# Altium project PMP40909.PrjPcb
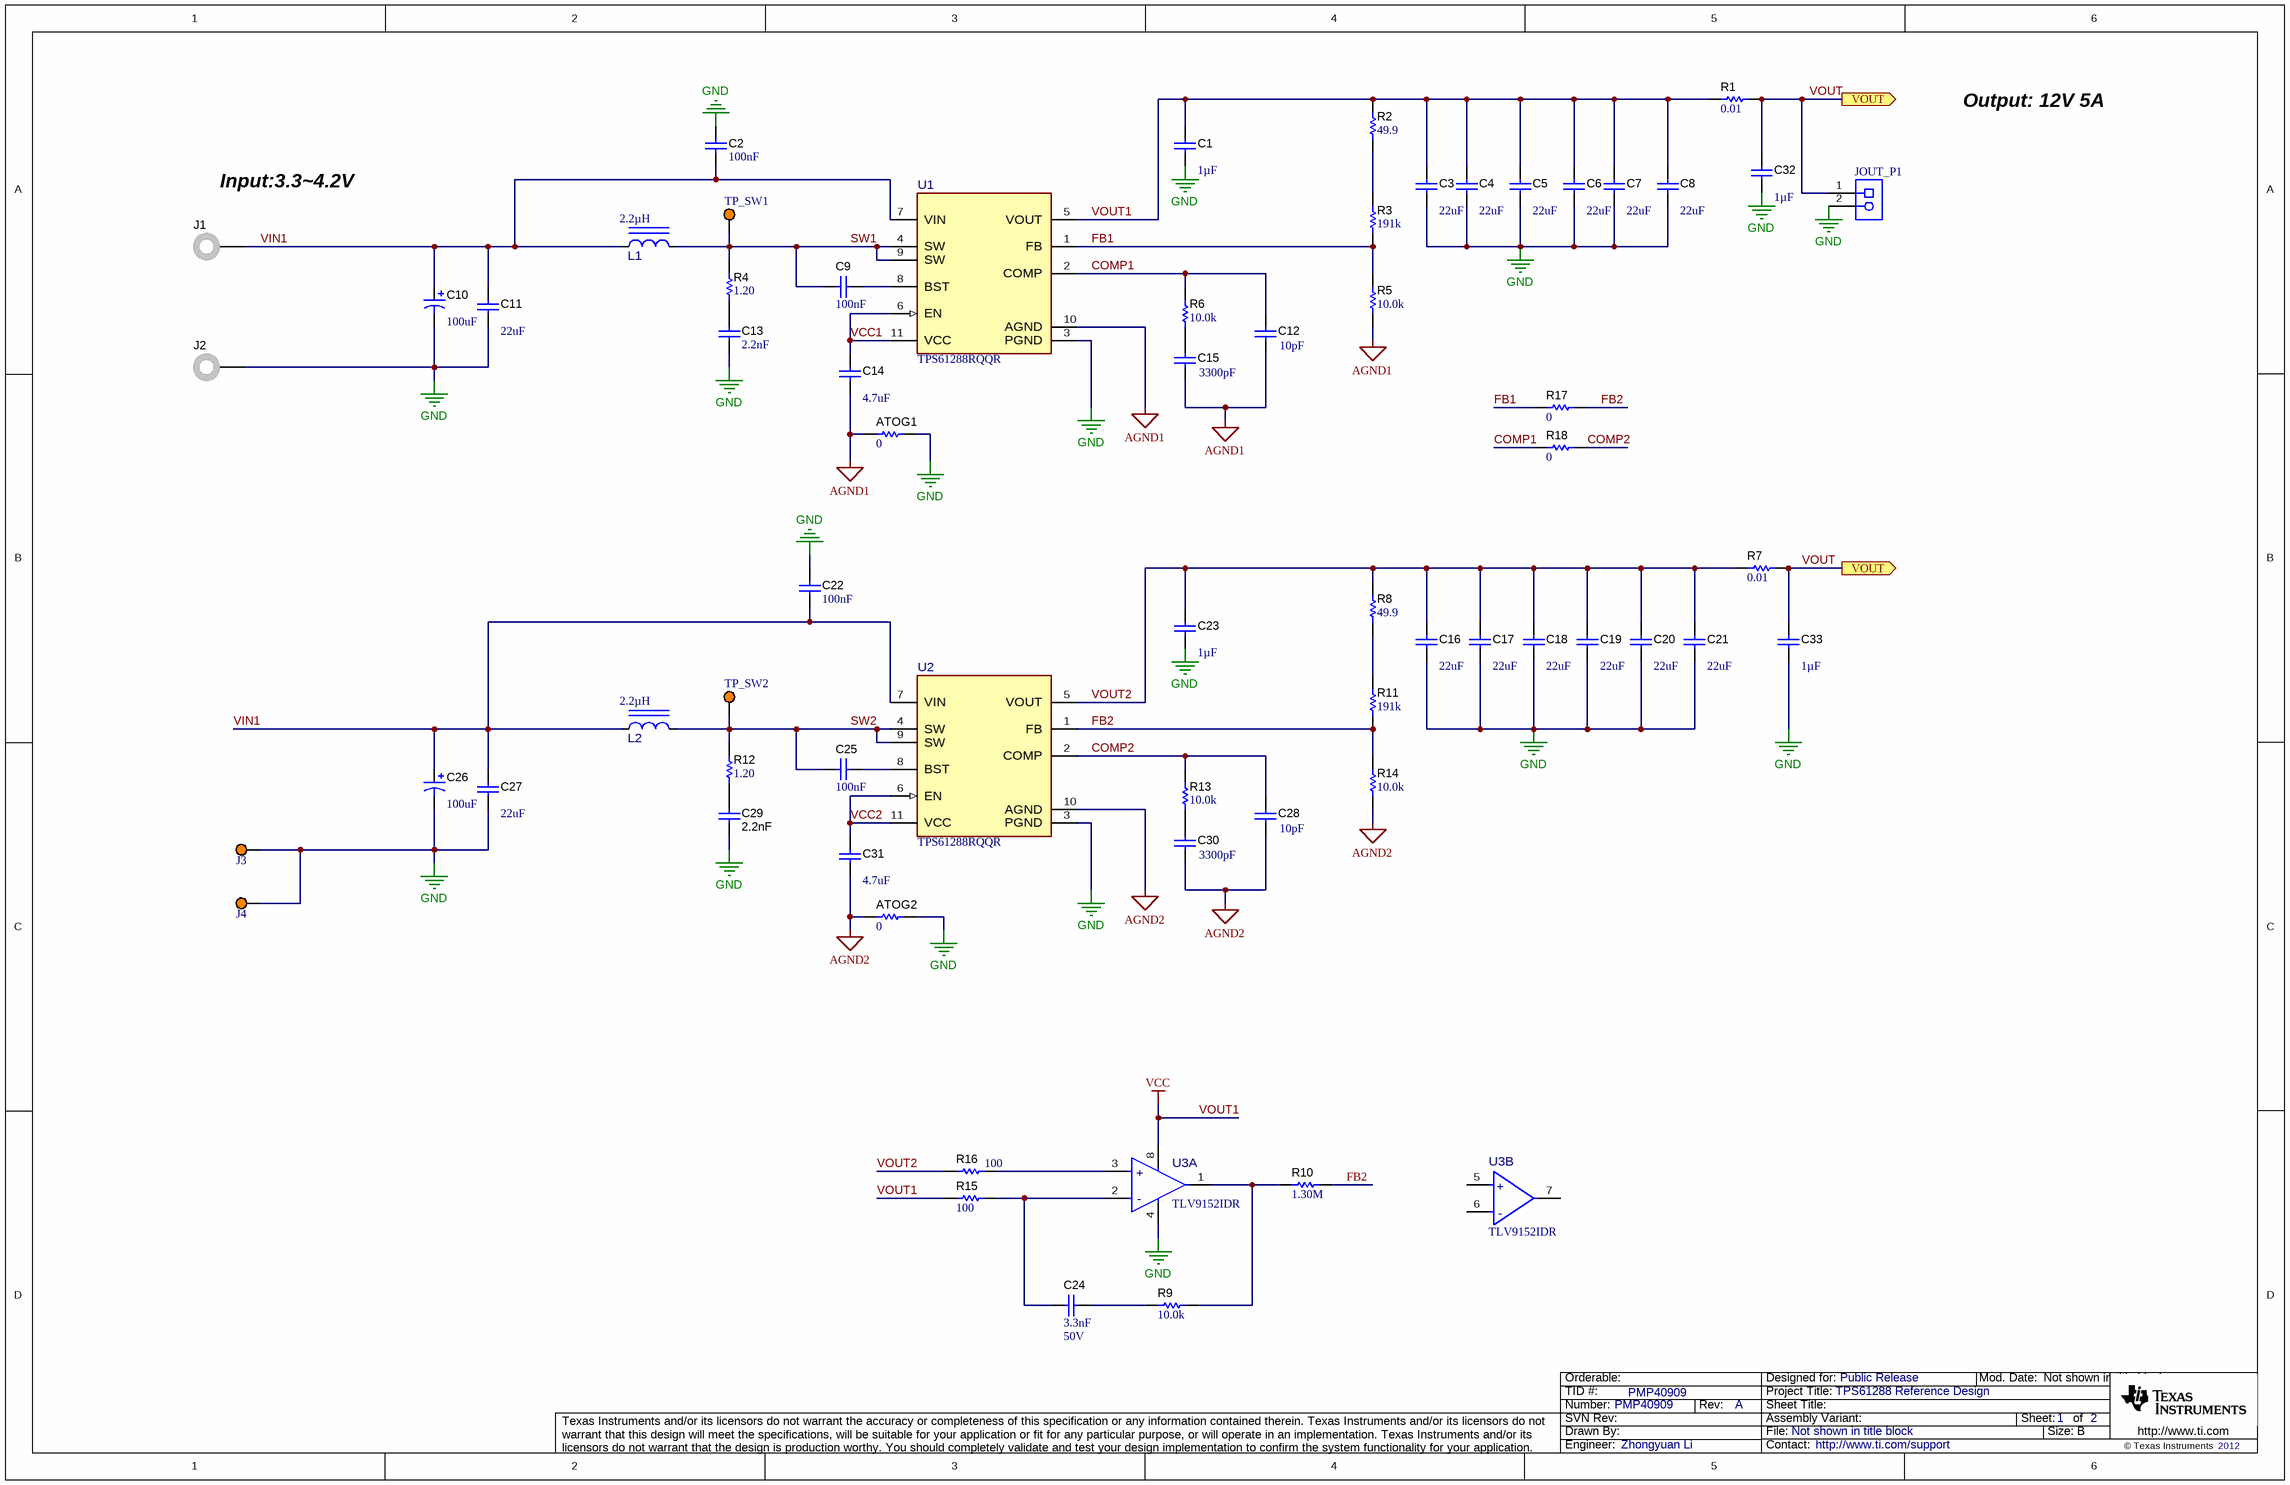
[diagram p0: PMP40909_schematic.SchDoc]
TID: PMP40909; TechSupport: http://www.ti.com/support; SCH_Rev: A; PRJ_Title: TPS61288 Reference Design; PRJ_Number: PMP40909; PRJ_Engineer: Zhongyuan Li; PRJ_Customer: Public Release; PCB_Rev: A; PCB_Layout: Zhongyuan Li; CopyrightYear: 2012
2 sheets, 68 parts. Net scope: flat (ports and power ports of the same name join across sheets).
Board file: PMP40909.PcbDoc
Sheets:
  PMP40909_schematic.SchDoc
  PMP40909_Hardware.SchDoc

## Sheet PMP40909_schematic.SchDoc
size 431 x 279 mm; Date: Not shown in title block; ApprovedBy: Not shown in title block; CheckedBy: Not shown in title block; Author: Not shown in title block; CompanyName: Not shown in title block; Engineer: Not shown in title block; Organization: Not shown in title block; Address1: Not shown in title block; Address2: Not shown in title block; Address3: Not shown in title block; Address4: Not shown in title block; DocumentNumber: 2; Revision: Use project parameter SCH_Rev; SheetNumber: 1; SheetTotal: 2; PageSetup: Record=PageOptions¦CenterHorizontal=True¦CenterVertical=True¦PrintScale=1.00¦XCorrection=1.00¦YCorrection=1.00¦PrintKind=0¦BorderSize=5000000¦LeftOffset=0¦BottomOffset=0¦Orientation=2¦PaperLength=1000¦PaperWidth=1000¦Scale=100¦PaperSource=15¦PrintQuality=600¦MediaType=1¦DitherType=10¦PaperKind=Letter¦PrintScaleMode=1

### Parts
ATOG1  ValueDisplayed: 0  [0603]  (hidden comment: RMCF0603ZT0R00)
ATOG2  ValueDisplayed: 0  [0603]  (hidden comment: RMCF0603ZT0R00)
C1  ValueDisplayed: 1µF  [0603]  (hidden comment: GRT188R61H105ME13D)
C2  Cap_F: 100nF  [0603]  (hidden comment: CGA3E2X7R1H104K080AA)
C3  ValueDisplayed: 22uF  [1210_270]  (hidden comment: GRM32ER71E226KE15L)
C4  ValueDisplayed: 22uF  [1210_270]  (hidden comment: GRM32ER71E226KE15L)
C5  ValueDisplayed: 22uF  [1210_270]  (hidden comment: GRM32ER71E226KE15L)
C6  ValueDisplayed: 22uF  [1210_270]  (hidden comment: GRM32ER71E226KE15L)
C7  ValueDisplayed: 22uF  [1210_270]  (hidden comment: GRM32ER71E226KE15L)
C8  ValueDisplayed: 22uF  [1210_270]  (hidden comment: GRM32ER71E226KE15L)
C9  Cap_F: 100nF  [0603]  (hidden comment: CGA3E2X7R1H104K080AA)
C10  ValueDisplayed: 100uF  [SM_RADIAL_6.3BMM]  (hidden comment: EEHZA1E101XP)
C11  ValueDisplayed: 22uF  [1210_270]  (hidden comment: GRM32ER71E226KE15L)
C12  ValueDisplayed: 10pF  [0603]  (hidden comment: GRM1885C1H100JA01D)
C13  Cap_F: 2.2nF  [0603]  (hidden comment: GRM188R72E222KW07D)
C14  ValueDisplayed: 4.7uF  [0603]  (hidden comment: 0603ZD475KAT2A)
C15  ValueDisplayed: 3300pF  [0603]  (hidden comment: GRM1885C1H332JA01D)
C16  ValueDisplayed: 22uF  [1210_270]  (hidden comment: GRM32ER71E226KE15L)
C17  ValueDisplayed: 22uF  [1210_270]  (hidden comment: GRM32ER71E226KE15L)
C18  ValueDisplayed: 22uF  [1210_270]  (hidden comment: GRM32ER71E226KE15L)
C19  ValueDisplayed: 22uF  [1210_270]  (hidden comment: GRM32ER71E226KE15L)
C20  ValueDisplayed: 22uF  [1210_270]  (hidden comment: GRM32ER71E226KE15L)
C21  ValueDisplayed: 22uF  [1210_270]  (hidden comment: GRM32ER71E226KE15L)
C22  Cap_F: 100nF  [0603]  (hidden comment: CGA3E2X7R1H104K080AA)
C23  ValueDisplayed: 1µF  [0603]  (hidden comment: GRT188R61H105ME13D)
C24  Cap_F: 3.3nF  VDC_V: 50V  [0603]  (hidden comment: C0603X332K5RACTU)
C25  Cap_F: 100nF  [0603]  (hidden comment: CGA3E2X7R1H104K080AA)
C26  ValueDisplayed: 100uF  [SM_RADIAL_6.3BMM]  (hidden comment: EEHZA1E101XP)
C27  ValueDisplayed: 22uF  [1210_270]  (hidden comment: GRM32ER71E226KE15L)
C28  ValueDisplayed: 10pF  [0603]  (hidden comment: GRM1885C1H100JA01D)
C29  Cap_F: 2.2nF  [0603]  (hidden comment: GRM188R72E222KW07D)
C30  ValueDisplayed: 3300pF  [0603]  (hidden comment: GRM1885C1H332JA01D)
C31  ValueDisplayed: 4.7uF  [0603]  (hidden comment: 0603ZD475KAT2A)
C32  ValueDisplayed: 1µF  [0603]  (hidden comment: GRT188R61H105ME13D)
C33  ValueDisplayed: 1µF  [0603]  (hidden comment: GRT188R61H105ME13D)
J1  108-0740-001  [Johnson_108-0740-001]  (value not drawn)
J2  108-0740-001  [Johnson_108-0740-001]  (value not drawn)
J3  5003  [Keystone5003]  (value not drawn)
J4  5003  [Keystone5003]  (value not drawn)
JOUT_P1  691214110002  [Wurth_691214110002]  (value not drawn)
L1  Ind_H: 2.2µH  [FP-CMLE105T-2R2MS-99_SMT_IND_11MM15_10MM0-MFG]  (hidden comment: CMLE105T-2R2MS-99)
L2  Ind_H: 2.2µH  [FP-CMLE105T-2R2MS-99_SMT_IND_11MM15_10MM0-MFG]  (hidden comment: CMLE105T-2R2MS-99)
R1  ValueDisplayed: 0.01  [2512]  (hidden comment: WSL2512R0100FEA)
R2  ValueDisplayed: 49.9  [0603]  (hidden comment: ERJ-3EKF49R9V)
R3  ValueDisplayed: 191k  [0603]  (hidden comment: CRCW0603191KFKEA)
R4  ValueDisplayed: 1.20  [1206]  (hidden comment: CRCW12061R20FKEA)
R5  ValueDisplayed: 10.0k  [0603]  (hidden comment: RCG060310K0FKEA)
R6  ValueDisplayed: 10.0k  [0603]  (hidden comment: CRCW060310K0FKEA)
R7  ValueDisplayed: 0.01  [2512]  (hidden comment: WSL2512R0100FEA)
R8  ValueDisplayed: 49.9  [0603]  (hidden comment: ERJ-3EKF49R9V)
R9  ValueDisplayed: 10.0k  [0603]  (hidden comment: RCG060310K0FKEA)
R10  ValueDisplayed: 1.30M  [0603]  (hidden comment: CRCW06031M30FKEA)
R11  ValueDisplayed: 191k  [0603]  (hidden comment: CRCW0603191KFKEA)
R12  ValueDisplayed: 1.20  [1206]  (hidden comment: CRCW12061R20FKEA)
R13  ValueDisplayed: 10.0k  [0603]  (hidden comment: CRCW060310K0FKEA)
R14  ValueDisplayed: 10.0k  [0603]  (hidden comment: RCG060310K0FKEA)
R15  ValueDisplayed: 100  [0603]  (hidden comment: ERJ-3EKF1000V)
R16  ValueDisplayed: 100  [0603]  (hidden comment: ERJ-3EKF1000V)
R17  ValueDisplayed: 0  [0603]  (hidden comment: RMCF0603ZT0R00)
R18  ValueDisplayed: 0  [0603]  (hidden comment: RMCF0603ZT0R00)
TP_SW1  5003  [Keystone5003]  (value not drawn)
TP_SW2  5003  [Keystone5003]  (value not drawn)
U1  TPS61288RQQR  [RQQ0011A-MFG]
U2  TPS61288RQQR  [RQQ0011A-MFG]
U3  TLV9152IDR  [D0008A-MFG]  (parts A,B of 2)

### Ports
VOUT (out)

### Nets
AGND1: ATOG1.2 C12.2 C14.1 C15.2 R5.2 U1.10(AGND)
AGND2: ATOG2.2 C28.2 C30.2 C31.1 R14.2 U2.10(AGND)
GND: ATOG1.1 ATOG2.1 C1.2 C2.1 C3.2 C4.2 C5.2 C6.2 C7.2 C8.2 C10.2(-) C11.2 C13.2 C16.1 C17.1 C18.1 C19.1 C20.1 C21.1 C22.1 C23.2 C26.2(-) C27.2 C29.2 C32.2 C33.2 J2.1 J3.1 J4.1 JOUT_P1.2 U1.3(PGND) U2.3(PGND) U3.4(V-)
VOUT1: C1.1 C3.1 C4.1 C5.1 C6.1 C7.1 C8.1 R1.1 R2.2 R15.1 U1.5(VOUT) U3.8(V+)  [also labelled VCC]
COMP1: C12.1 R6.2 R18.2 U1.2(COMP)
COMP2: C28.1 R13.2 R18.1 U2.2(COMP)
FB1: R3.1 R5.1 R17.2 U1.1(FB)
FB2: R10.2 R11.1 R14.1 R17.1 U2.1(FB)
SW1: C9.1 L1.2 R4.1 TP_SW1.1 U1.4(SW) U1.9(SW)
SW2: C25.1 L2.2 R12.1 TP_SW2.1 U2.4(SW) U2.9(SW)
VCC1: C14.2 U1.6(EN) U1.11(VCC)
VCC2: C31.2 U2.6(EN) U2.11(VCC)
VIN1: C2.2 C10.1(+) C11.1 C22.2 C26.1(+) C27.1 J1.1 L1.1 L2.1 U1.7(VIN) U2.7(VIN)
VOUT: C32.1 C33.1 JOUT_P1.1 R1.2 R7.2 ; port VOUT
VOUT2: C16.2 C17.2 C18.2 C19.2 C20.2 C21.2 C23.1 R7.1 R8.1 R16.1 U2.5(VOUT)
NetC9_2: C9.2 U1.8(BST)
NetC13_1: C13.1 R4.2
NetC15_1: C15.1 R6.1
NetC24_1: C24.1 R9.1
NetC24_2: C24.2 R15.2 U3.2(IN1-)
NetC25_2: C25.2 U2.8(BST)
NetC29_1: C29.1 R12.2
NetC30_1: C30.1 R13.1
NetR2_1: R2.1 R3.2
NetR8_2: R8.2 R11.2
NetR9_2: R9.2 R10.1 U3.1(OUT1)
NetR16_2: R16.2 U3.3(IN1+)

Not connected (* = marked no-connect by the designer): U3 5(IN2+) 6(IN2-) 7(OUT2)

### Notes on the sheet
- Output: 12V 5A
- Input:3.3~4.2V

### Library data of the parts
ATOG1 ATOG2 R17 R18 = CMP-0023343-2: RES, 0, 1%, 0.1 W, AEC-Q200 Grade 0, 0603; Manufacturer: Stackpole Electronics Inc; Power_W: 100mW; TempCo: ppm/C; U/M: EA; Value: 0; SizeX_mm: 1.6; SizeY_mm: 0.8; SizeZ_mm: 1; Value2: 0.1W; SizeArea_mm2: 1.28; AEC Qualified: Y; AEC Category: Q200
C1 C23 C32 C33 = CMP-0081784-1: CAP, CERM, 1 µF, 50 V,+/- 20%, X5R, AEC-Q200 Grade 3, 0603; Manufacturer: MuRata; TaMin_C: -55°C; Polarized: N; SizeAreaWB_mm2: 4.68; U/M: EA; Value: 1uF; TaMax_C: 85°C; SizeZ_mm: 1; SizeX_mm: 1.6; SizeY_mm: 0.8; Value2: 50V; SizeArea_mm2: 1.28; AEC Qualified: Y; AEC Grade: 3; AEC Category: Q200
C2 C9 C22 C25 = CMP-0007078-2: CAP, CERM, 0.1 uF, 50 V, +/- 10%, X7R, AEC-Q200 Grade 1, 0603; Manufacturer: TDK; TaMin_C: -55°C; ESR_ohm: 0.0296; Polarized: N; SizeAreaWB_mm2: 4.68; Value1: 0.0296 ohm; U/M: EA; Value: 0.1uF; TaMax_C: 125°C; SizeZ_mm: 1; SizeX_mm: 1.6; SizeY_mm: 0.8; Value2: 50V; SizeArea_mm2: 1.28; AEC Qualified: Y; IRMS_A: 971.99mA; AEC Category: Q200
C3-C8 C11 C16-C21 C27 = CMP-0009224-2: CAP, CERM, 22 uF, 25 V, +/- 10%, X7R, 1210; Manufacturer: MuRata; TaMin_C: -55°C; Polarized: N; SizeAreaWB_mm2: 14.7; Value1: Unknown; U/M: EA; Value: 22uF; TaMax_C: 125°C; SizeZ_mm: 2.7; SizeX_mm: 3.2; SizeY_mm: 2.5; Cap_Case: 1210; Value2: 25V; SizeArea_mm2: 8; Cap_F: 22µF; AEC Category: Q200
C10 C26 = CMP-0012570-3: CAP, Polymer Hybrid, 100 uF, 25 V, +/- 20%, 30 ohm, 6.3x7.7 SMD; Manufacturer: Panasonic; TaMin_C: -55°C; ESR_ohm: 30; Polarized: Y; SizeAreaWB_mm2: 79.98; Value1: 30 ohm; Value: 100uF; TaMax_C: 105°C; SizeZ_mm: 7.7; SizeX_mm: 7.3; SizeY_mm: 6.6; Value2: 25V; SizeArea_mm2: 48.18; CompType: Capacitor; Cap_F: 100µF; IRMS_A: 2A; AEC Category: Q200
C12 C28 = CMP-0007170-4: CAP, CERM, 10 pF, 50 V, +/- 5%, C0G/NP0, 0603; Manufacturer: MuRata; TaMin_C: -55°C; Polarized: N; SizeAreaWB_mm2: 4.68; Value1: Unknown; U/M: EA; Value: 10pF; TaMax_C: 125°C; SizeZ_mm: 1; SizeX_mm: 1.6; SizeY_mm: 0.8; Value2: 50V; SizeArea_mm2: 1.28; AEC Category: Q200
C13 C29 = CMP-0007493-2: CAP, CERM, 2200 pF, 250 V, +/- 10%, X7R, 0603; Manufacturer: MuRata; TaMin_C: -55°C; Polarized: N; SizeAreaWB_mm2: 4.68; Value1: Unknown; U/M: EA; Value: 2200pF; TaMax_C: 125°C; SizeZ_mm: 1; SizeX_mm: 1.6; SizeY_mm: 0.8; Value2: 250V; SizeArea_mm2: 1.28; AEC Category: Q200
C14 C31 = CMP-0006816-5: CAP, CERM, 4.7 uF, 10 V, +/- 10%, X5R, 0603; Manufacturer: AVX; TaMin_C: -55°C; Polarized: N; SizeAreaWB_mm2: 4.68; Value1: Unknown; U/M: EA; Value: 4.7uF; TaMax_C: 85°C; SizeZ_mm: 1; SizeX_mm: 1.6; SizeY_mm: 0.8; Value2: 10V; SizeArea_mm2: 1.28; Cap_F: 4.7µF; AEC Category: Q200
C15 C30 = CMP-0007210-4: CAP, CERM, 3300 pF, 50 V, +/- 5%, C0G/NP0, 0603; Manufacturer: MuRata; TaMin_C: -55°C; Polarized: N; SizeAreaWB_mm2: 4.68; Value1: Unknown; U/M: EA; Value: 3300pF; TaMax_C: 125°C; SizeZ_mm: 1; SizeX_mm: 1.6; SizeY_mm: 0.8; Value2: 50V; SizeArea_mm2: 1.28; Cap_F: 3.3nF; AEC Category: Q200
C24 = CMP-0006985-2: CAP, CERM, 3300 pF, 50 V, +/- 10%, X7R, 0603; Manufacturer: Kemet; TaMin_C: -55°C; Polarized: N; SizeAreaWB_mm2: 4.68; Value1: Unknown; U/M: EA; Value: 3300pF; TaMax_C: 125°C; SizeZ_mm: 1; SizeX_mm: 1.6; SizeY_mm: 0.8; SizeArea_mm2: 1.28; AEC Category: Q200
J1 J2 = CMP-0055387-2: Standard Banana Jack, Uninsulated, 15A; Manufacturer: Cinch Connectivity; CNHeader: FALSE; Green_Lifecycle: Active; Green_REACh: Passed; CT: TRUE
J3 J4 TP_SW1 TP_SW2 = CMP-0055140-1: Test Point, Miniature, Orange, TH; Manufacturer: Keystone; CNHeader: FALSE; Green_Lifecycle: Active; Green_REACh: Passed; ContactFinish: Silver; CT: TRUE
JOUT_P1 = CMP-0054825-2: Terminal Block, 3.5mm, 2x1, Tin, TH; Manufacturer: Wurth Elektronik; Pitch_mm: 3.5; CT: TRUE; CNHeader: FALSE; Voltage_V: 300V; Gender: Female; Cert_UL: Y; Row_Count: 1; Current_A: 10A
L1 L2 = CMP-0089717-1: Fixed Inductor 2.2uH 20% 100kHz 19.5A 4.5mOhm; Manufacturer: Cyntec; DCR_ohm: 4.5m; Material: Metal Dust; Isat: 22A; SizeZ_mm: 4mm; Standoff Height: 0mm; AEC Qualified: No
R1 R7 = CMP-0015850-2: RES, 0.01, 1%, 1 W, 2512; Manufacturer: Vishay-Dale; Power_W: 1W; TempCo: 75 ppm/C; Value_Code: R010; U/M: EA; Value: 0.01; EIA_Code: E96; SizeX_mm: 6.3; SizeY_mm: 3.2; SizeZ_mm: 0.71; SizeArea_mm2: 20.16; AEC Category: Q200
R2 R8 = CMP-0022707-2: RES, 49.9, 1%, 0.1 W, AEC-Q200 Grade 0, 0603; Manufacturer: Panasonic; Power_W: 100mW; Value_Code: 49R9; U/M: EA; Value: 49.9; EIA_Code: E96; TempCo: 100 ppm/C; SizeX_mm: 1.6; SizeY_mm: 0.8; SizeZ_mm: 1; Value2: 0.1W; SizeArea_mm2: 1.28; AEC Qualified: Y; AEC Grade: 0; AEC Category: Q200
R3 R11 = CMP-0022101-4: RES, 191 k, 1%, 0.1 W, AEC-Q200 Grade 0, 0603; Manufacturer: Vishay-Dale; Power_W: 100mW; TempCo: 100 ppm/C; Value: 191k; EIA_Code: E96; SizeX_mm: 1.6; SizeY_mm: 0.8; SizeZ_mm: 1; Value2: 0.1W; SizeArea_mm2: 1.28; AEC Qualified: Y; VDC_V: 75V; AEC Category: Q200; AEC Grade: 0
R4 R12 = CMP-0016753-2: RES, 1.20, 1%, 0.25 W, AEC-Q200 Grade 0, 1206; Manufacturer: Vishay-Dale; Power_W: 250mW; TempCo: 100 ppm/C; Value_Code: 1R20; U/M: EA; Value: 1.20; Res_ohm: 1.2; SizeX_mm: 3.2; SizeY_mm: 1.6; SizeZ_mm: 1.35; Value2: 0.25W; SizeArea_mm2: 5.12; AEC Qualified: Y; VDC_V: 200V; AEC Grade: 0; AEC Category: Q200
R5 R9 R14 = CMP-0023337-2: RES, 10.0 k, 1%, 0.1 W, 0603; Manufacturer: Vishay Draloric; Power_W: 100mW; TempCo: 100 ppm/C; Value_Code: 10k0; U/M: EA; Value: 10.0k; EIA_Code: E96; Res_ohm: 10k; SizeX_mm: 1.6; SizeY_mm: 0.8; SizeZ_mm: 1; Value2: 0.1W; SizeArea_mm2: 1.28; AEC Qualified: N; VDC_V: 75V; AEC Category: Q200
R6 R13 = CMP-0021998-4: RES, 10.0 k, 1%, 0.1 W, AEC-Q200 Grade 0, 0603; Manufacturer: Vishay-Dale; Power_W: 100mW; TempCo: 100 ppm/C; Value_Code: 10k0; Value: 10.0k; EIA_Code: E96; Res_ohm: 10k; SizeX_mm: 1.6; SizeY_mm: 0.8; SizeZ_mm: 1; Value2: 0.1W; SizeArea_mm2: 1.28; AEC Qualified: Y; VDC_V: 75V; AEC Category: Q200; AEC Grade: 0
R10 = CMP-0022150-2: RES, 1.30 M, 1%, 0.1 W, 0603; Manufacturer: Vishay-Dale; Power_W: 100mW; TempCo: 100 ppm/C; Value_Code: 1M30; U/M: EA; Value: 1.30Meg; EIA_Code: E96; Res_ohm: 1.3M; SizeX_mm: 1.6; SizeY_mm: 0.8; SizeZ_mm: 1; Value2: 0.1W; SizeArea_mm2: 1.28; VDC_V: 75V; AEC Category: Q200
R15 R16 = CMP-0022679-2: RES, 100, 1%, 0.1 W, AEC-Q200 Grade 0, 0603; Manufacturer: Panasonic; Power_W: 100mW; TempCo: 100 ppm/C; Value_Code: 100R; U/M: EA; Value: 100; EIA_Code: E96; SizeX_mm: 1.6; SizeY_mm: 0.8; SizeZ_mm: 1; Value2: 0.1W; SizeArea_mm2: 1.28; AEC Qualified: Y; AEC Grade: 0; AEC Category: Q200
U1 U2 = CMP-0089018-1: Fully Integrated Synchronous Boost Converter; Manufacturer: Texas Instruments; SizeZ_mm: 1mm; AEC Qualified: No
U3 = CMP-0091916-1: General Purpose Amplifier 2 Circuit Rail-to-Rail 8-SOIC; Manufacturer: Texas Instruments; Number Of Channels: 2; Gain Bandwidth: 4.5MHz; TaMin_C: -40°C; Max Dual Supply Voltage: 8V; Max Supply Voltage: 16V; Output Current Per Channel: 75mA; Input Offset Voltage: 0.125mV; TaMax_C: +125°C; Min Dual Supply Voltage: 1.35V; Nominal Supply Current: 30-560uA; Min Supply Voltage: 2.7V; TJmax_C: +150°C; AEC Qualified: No; Response Time: 2.5us; SizeZ_mm: 1.75mm; Input Bias Current: 0.00001uA; Standoff Height: 0.11mm

## Sheet PMP40909_Hardware.SchDoc
size 431 x 279 mm; Date: Not shown in title block; ApprovedBy: Not shown in title block; CheckedBy: Not shown in title block; Author: Not shown in title block; CompanyName: Not shown in title block; Engineer: Not shown in title block; Organization: Not shown in title block; Address1: Not shown in title block; Address2: Not shown in title block; Address3: Not shown in title block; Address4: Not shown in title block; DocumentNumber: 3; Revision: Use project parameter SCH_Rev; SheetNumber: 2; SheetTotal: 2; PageSetup: Record=PageOptions¦CenterHorizontal=True¦CenterVertical=True¦PrintScale=1.00¦XCorrection=1.00¦YCorrection=1.00¦PrintKind=0¦BorderSize=5000000¦LeftOffset=0¦BottomOffset=0¦Orientation=2¦PaperLength=1000¦PaperWidth=1000¦Scale=100¦PaperSource=15¦PrintQuality=600¦MediaType=1¦DitherType=10¦PaperKind=Letter¦PrintScaleMode=1
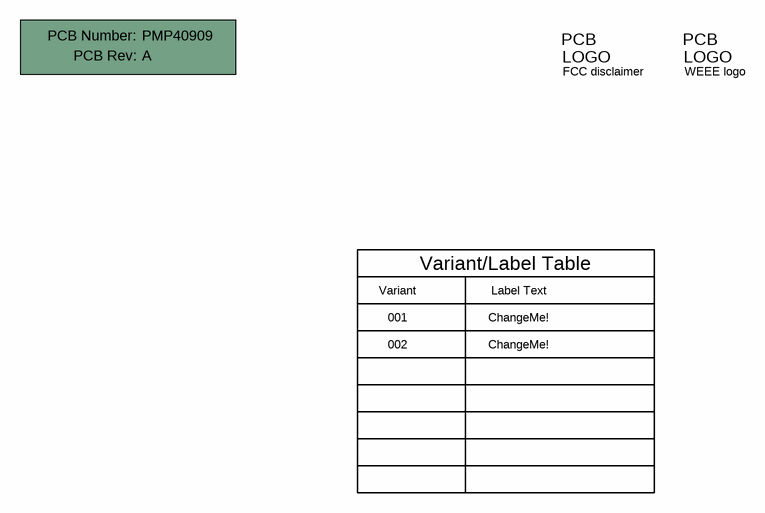
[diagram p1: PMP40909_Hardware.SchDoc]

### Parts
!PCB  Printed Circuit Board  (value not drawn)  (mechanical)
Logo3  FCC disclaimer  [FCC_disclaimer]  (no BOM)
Logo4  WEEE logo  [WEEE_Minimum]  (no BOM)

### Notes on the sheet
- Variant
- Variant/Label Table
- Label Text
- 001
- 002
- ChangeMe!

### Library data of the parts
!PCB = CMP-0003618-2: Manufacturer: Any; PartNumber: PMP40909
Logo3 = CMP-0074847-1: FCC_disclaimer; Library Reference: Logo
Logo4 = CMP-0074769-1

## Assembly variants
001: not fitted C13 C24 C28 C29 C30 R4 R8 R9 R10 R11 R12 R13 R14 R15 R16 U3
